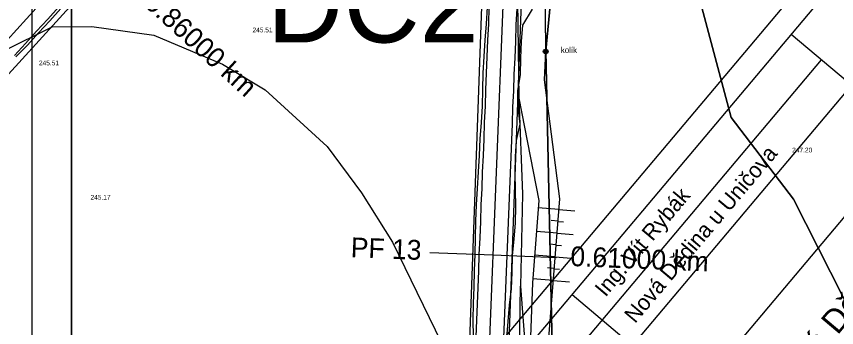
# Model space of a CAD drawing. Extents: x -555887 to -552101, y -1100251 to -1096546.
# Drawn here: x -554315.6 to -554212, y -1097004.2 to -1096964.9 of the extents above; entities that cross this region are included whole.
import ezdxf

# ---------------------------------------------------------------- set-up
doc = ezdxf.new("R2010")
doc.units = 0
for name, color, linetype in [('PARCELY_cesty', 7, 'Continuous'), ('PARCELY_VHO', 7, 'Continuous'), ('POLYGONY_POPIS_CESTY', 7, 'Continuous'), ('POLYGONY_SITUACE_PF', 7, 'Continuous'), ('POLYGONY_SITUACE_PF_POPISY', 7, 'Continuous'), ('POLYGONY_SITUACE_PO', 7, 'Continuous'), ('ram_VC2', 7, 'Continuous'), ('ram_VC6', 7, 'Continuous'), ('vrstevnice', 7, 'Continuous'), ('Výškopis', 7, 'Continuous'), ('ZSST', 7, 'Continuous'), ('zájem', 7, 'Continuous')]:
    doc.layers.add(name, color=color, linetype=linetype)

msp = doc.modelspace()

# ---------------------------------------------------------------- linework, layer by layer
at = {"layer": 'PARCELY_cesty'}
for points in [[(-554879.07, -1097590.15), (-554550.67, -1097229.32), (-554531.76, -1097208.54), (-554275.81, -1096927.3), (-554273.04, -1096923.94), (-554268.63, -1096916.51), (-554265.12, -1096907.97), (-554264.18, -1096901.52)], [(-554235.26, -1097250.21), (-554222.33, -1097095.1), (-554222.18, -1097088.53), (-554223.59, -1097078.8), (-554226.63, -1097069.37), (-554233.34, -1097058.26), (-554245.88, -1097042.06), (-554250.33, -1097033.26), (-554252.75, -1097025.27), (-554253.64, -1097013.94), (-554251.14, -1096944.55), (-554252.47, -1096936.15), (-554254.99, -1096928.04), (-554262.23, -1096914.12), (-554265.12, -1096907.97)], [(-554240.16, -1097243.28), (-554227.33, -1097094.83), (-554227.19, -1097088.83), (-554228.48, -1097079.94), (-554231.21, -1097071.46), (-554237.47, -1097061.09), (-554250.13, -1097044.74), (-554254.99, -1097035.13), (-554257.7, -1097026.2), (-554258.64, -1097014.04), (-554256.15, -1096944.85), (-554257.35, -1096937.29), (-554259.63, -1096929.97), (-554262.61, -1096924.34), (-554273.04, -1096923.94)]]:
    msp.add_lwpolyline(points, dxfattribs=at)
at = {"layer": 'PARCELY_VHO'}
for points in [[(-554130.46, -1097180.06), (-554159.17, -1097101.34), (-554159.64, -1097082.93), (-554163.72, -1097067.19), (-554173.74, -1097050.79), (-554190.63, -1097034.96), (-554197.16, -1097028.05), (-554217.46, -1096987.98), (-554225.33, -1096977.64), (-554234.21, -1096944.26), (-554236.99, -1096909.92), (-554235.22, -1096898.62), (-554228.6, -1096882.13), (-554225.73, -1096869.26), (-554224.9, -1096864.61), (-554220.11, -1096846.63), (-554200.4, -1096831.93), (-554179.17, -1096807.62), (-554142.08, -1096773.53), (-554110.69, -1096747.36), (-554089.18, -1096729.49)], [(-554235.26, -1097250.21), (-554222.33, -1097095.1), (-554222.18, -1097088.53), (-554223.59, -1097078.8), (-554226.63, -1097069.37), (-554233.34, -1097058.26), (-554245.88, -1097042.06), (-554250.33, -1097033.26), (-554252.75, -1097025.27), (-554253.64, -1097013.94), (-554251.14, -1096944.55), (-554252.47, -1096936.15), (-554254.99, -1096928.04), (-554262.23, -1096914.12), (-554265.12, -1096907.97), (-554264.18, -1096901.52), (-554256.59, -1096884.82), (-554225.08, -1096837.14), (-554208.2, -1096823.7)], [(-554200.4, -1096831.93), (-554220.11, -1096846.63), (-554224.9, -1096864.61), (-554233.29, -1096868.06), (-554243.42, -1096872.22), (-554247.48, -1096879.5), (-554255.66, -1096892.57), (-554260.45, -1096913.44), (-554248.68, -1096931.61), (-554247, -1096951.09), (-554248.74, -1096969.23), (-554247.82, -1097012.49), (-554234.69, -1097042.48), (-554228.63, -1097050.04), (-554218.79, -1097074.22), (-554216.52, -1097103.52), (-554219.47, -1097120.44), (-554219.42, -1097159.44)]]:
    msp.add_lwpolyline(points, dxfattribs=at)
at = {"layer": 'POLYGONY_SITUACE_PF'}
for p, q in [((-554263.37, -1096994.69), (-554255.38, -1096995.02)), ((-554255.38, -1096995.02), (-554247.38, -1096995.34))]:
    msp.add_line(p, q, dxfattribs=at)
at = {"layer": 'POLYGONY_SITUACE_PO'}
for p, q in [((-554884.96, -1097592.18), (-554278.08, -1096925.34)), ((-554256.14, -1097013.99), (-554253.57, -1096950.09)), ((-554311.64, -1096965.2), (-554310.24, -1096963.66)), ((-554311.64, -1096965.2), (-554310.24, -1096963.66)), ((-554311.39, -1096965.42), (-554310, -1096963.88)), ((-554256.24, -1096965.79), (-554256.09, -1096963.71)), ((-554255.95, -1096965.8), (-554255.87, -1096963.72)), ((-554255.95, -1096965.8), (-554255.87, -1096963.72)), ((-554252.46, -1096965.94), (-554252.37, -1096963.86)), ((-554252.46, -1096965.94), (-554252.37, -1096963.86)), ((-554251.63, -1096965.98), (-554250.4, -1096963.94)), ((-554313.05, -1096966.74), (-554311.64, -1096965.2)), ((-554313.05, -1096966.74), (-554311.64, -1096965.2)), ((-554312.82, -1096966.94), (-554311.39, -1096965.42)), ((-554256.4, -1096967.87), (-554256.24, -1096965.79)), ((-554256.04, -1096967.88), (-554255.95, -1096965.8)), ((-554256.04, -1096967.88), (-554255.95, -1096965.8)), ((-554252.54, -1096968.03), (-554252.46, -1096965.94)), ((-554252.54, -1096968.03), (-554252.46, -1096965.94)), ((-554251.82, -1096968.05), (-554251.63, -1096965.98)), ((-554314.45, -1096968.28), (-554313.05, -1096966.74)), ((-554314.45, -1096968.28), (-554313.05, -1096966.74)), ((-554314.21, -1096968.5), (-554312.82, -1096966.94)), ((-554256.52, -1096969.95), (-554256.4, -1096967.87)), ((-554256.12, -1096969.97), (-554256.04, -1096967.88)), ((-554256.12, -1096969.97), (-554256.04, -1096967.88)), ((-554252.62, -1096970.11), (-554252.54, -1096968.03)), ((-554252.62, -1096970.11), (-554252.54, -1096968.03)), ((-554251.89, -1096970.14), (-554251.82, -1096968.05)), ((-554315.85, -1096969.82), (-554314.45, -1096968.28)), ((-554315.85, -1096969.82), (-554314.45, -1096968.28)), ((-554315.67, -1096969.98), (-554314.21, -1096968.5)), ((-554256.63, -1096972.03), (-554256.52, -1096969.95)), ((-554256.21, -1096972.05), (-554256.12, -1096969.97)), ((-554256.21, -1096972.05), (-554256.12, -1096969.97)), ((-554252.71, -1096972.19), (-554252.62, -1096970.11)), ((-554252.71, -1096972.19), (-554252.62, -1096970.11)), ((-554251.93, -1096972.22), (-554251.89, -1096970.14)), ((-554256.69, -1096974.11), (-554256.63, -1096972.03)), ((-554256.29, -1096974.13), (-554256.21, -1096972.05)), ((-554256.29, -1096974.13), (-554256.21, -1096972.05)), ((-554252.79, -1096974.27), (-554252.71, -1096972.19)), ((-554252.79, -1096974.27), (-554252.71, -1096972.19)), ((-554252.27, -1096974.29), (-554251.93, -1096972.22)), ((-554256.74, -1096976.2), (-554256.69, -1096974.11)), ((-554256.37, -1096976.21), (-554256.29, -1096974.13)), ((-554256.37, -1096976.21), (-554256.29, -1096974.13)), ((-554252.88, -1096976.35), (-554252.79, -1096974.27)), ((-554252.88, -1096976.35), (-554252.79, -1096974.27)), ((-554252.24, -1096976.38), (-554252.27, -1096974.29)), ((-554256.87, -1096978.28), (-554256.74, -1096976.2)), ((-554256.46, -1096978.29), (-554256.37, -1096976.21)), ((-554256.46, -1096978.29), (-554256.37, -1096976.21)), ((-554252.96, -1096978.43), (-554252.88, -1096976.35)), ((-554252.96, -1096978.43), (-554252.88, -1096976.35)), ((-554251.97, -1096978.47), (-554252.24, -1096976.38)), ((-554257.01, -1096980.36), (-554256.87, -1096978.28)), ((-554256.54, -1096980.37), (-554256.46, -1096978.29)), ((-554256.54, -1096980.37), (-554256.46, -1096978.29)), ((-554253.04, -1096980.51), (-554252.96, -1096978.43)), ((-554253.04, -1096980.51), (-554252.96, -1096978.43)), ((-554252.45, -1096980.54), (-554251.97, -1096978.47)), ((-554257.12, -1096982.44), (-554257.01, -1096980.36)), ((-554256.62, -1096982.46), (-554256.54, -1096980.37)), ((-554256.62, -1096982.46), (-554256.54, -1096980.37)), ((-554253.13, -1096982.6), (-554253.04, -1096980.51)), ((-554253.13, -1096982.6), (-554253.04, -1096980.51)), ((-554252.55, -1096982.62), (-554252.45, -1096980.54)), ((-554257.23, -1096984.52), (-554257.12, -1096982.44)), ((-554256.71, -1096984.54), (-554256.62, -1096982.46)), ((-554256.71, -1096984.54), (-554256.62, -1096982.46)), ((-554253.21, -1096984.68), (-554253.13, -1096982.6)), ((-554253.21, -1096984.68), (-554253.13, -1096982.6)), ((-554252.62, -1096984.7), (-554252.55, -1096982.62)), ((-554257.36, -1096986.6), (-554257.23, -1096984.52)), ((-554256.79, -1096986.62), (-554256.71, -1096984.54)), ((-554256.79, -1096986.62), (-554256.71, -1096984.54)), ((-554253.29, -1096986.76), (-554253.21, -1096984.68)), ((-554253.29, -1096986.76), (-554253.21, -1096984.68)), ((-554252.58, -1096986.79), (-554252.62, -1096984.7)), ((-554257.5, -1096988.68), (-554257.36, -1096986.6)), ((-554256.88, -1096988.7), (-554256.79, -1096986.62)), ((-554256.88, -1096988.7), (-554256.79, -1096986.62)), ((-554253.38, -1096988.84), (-554253.29, -1096986.76)), ((-554253.38, -1096988.84), (-554253.29, -1096986.76)), ((-554252.52, -1096988.88), (-554252.58, -1096986.79)), ((-554257.57, -1096990.76), (-554257.5, -1096988.68)), ((-554256.96, -1096990.78), (-554256.88, -1096988.7)), ((-554256.96, -1096990.78), (-554256.88, -1096988.7)), ((-554253.46, -1096990.92), (-554253.38, -1096988.84)), ((-554253.46, -1096990.92), (-554253.38, -1096988.84)), ((-554252.58, -1096990.96), (-554252.52, -1096988.88)), ((-554257.63, -1096992.84), (-554257.57, -1096990.76)), ((-554257.04, -1096992.86), (-554256.96, -1096990.78)), ((-554257.04, -1096992.86), (-554256.96, -1096990.78)), ((-554253.55, -1096993), (-554253.46, -1096990.92)), ((-554253.55, -1096993), (-554253.46, -1096990.92)), ((-554252.75, -1096993.04), (-554252.58, -1096990.96)), ((-554257.67, -1096994.92), (-554257.63, -1096992.84)), ((-554257.13, -1096994.95), (-554257.04, -1096992.86)), ((-554257.13, -1096994.95), (-554257.04, -1096992.86)), ((-554253.63, -1096995.09), (-554253.55, -1096993)), ((-554253.63, -1096995.09), (-554253.55, -1096993)), ((-554252.93, -1096995.11), (-554252.75, -1096993.04)), ((-554257.72, -1096997.01), (-554257.67, -1096994.92)), ((-554257.21, -1096997.03), (-554257.13, -1096994.95)), ((-554257.21, -1096997.03), (-554257.13, -1096994.95)), ((-554253.71, -1096997.17), (-554253.63, -1096995.09)), ((-554253.71, -1096997.17), (-554253.63, -1096995.09)), ((-554252.98, -1096997.2), (-554252.93, -1096995.11)), ((-554257.78, -1096999.09), (-554257.72, -1096997.01)), ((-554257.29, -1096999.11), (-554257.21, -1096997.03)), ((-554257.29, -1096999.11), (-554257.21, -1096997.03)), ((-554253.8, -1096999.25), (-554253.71, -1096997.17)), ((-554253.8, -1096999.25), (-554253.71, -1096997.17)), ((-554253.08, -1096999.28), (-554252.98, -1096997.2)), ((-554257.85, -1097001.17), (-554257.78, -1096999.09)), ((-554257.38, -1097001.19), (-554257.29, -1096999.11)), ((-554257.38, -1097001.19), (-554257.29, -1096999.11)), ((-554253.88, -1097001.33), (-554253.8, -1096999.25)), ((-554253.88, -1097001.33), (-554253.8, -1096999.25)), ((-554253.31, -1097001.35), (-554253.08, -1096999.28)), ((-554257.89, -1097003.26), (-554257.85, -1097001.17)), ((-554257.46, -1097003.27), (-554257.38, -1097001.19)), ((-554257.46, -1097003.27), (-554257.38, -1097001.19)), ((-554253.96, -1097003.41), (-554253.88, -1097001.33)), ((-554253.96, -1097003.41), (-554253.88, -1097001.33)), ((-554253.49, -1097003.43), (-554253.31, -1097001.35)), ((-554257.85, -1097005.34), (-554257.89, -1097003.26)), ((-554257.55, -1097005.35), (-554257.46, -1097003.27)), ((-554257.55, -1097005.35), (-554257.46, -1097003.27)), ((-554254.05, -1097005.49), (-554253.96, -1097003.41)), ((-554254.05, -1097005.49), (-554253.96, -1097003.41)), ((-554253.64, -1097005.51), (-554253.49, -1097003.43))]:
    msp.add_line(p, q, dxfattribs=at)
at = {"layer": 'ram_VC2'}
for p, q in [((-554279.7, -1097071.82), (-554163.8, -1096934.09)), ((-554217.74, -1096967.12), (-554171.83, -1097005.76)), ((-554291.17, -1097062.16), (-554213.91, -1096970.34)), ((-554287.35, -1097065.38), (-554210.09, -1096973.56)), ((-554245.42, -1097000.02), (-554237.77, -1097006.46))]:
    msp.add_line(p, q, dxfattribs=at)
for points in [[(-554299.23, -1097059.3), (-554179.47, -1096916.99), (-554128.97, -1096959.48), (-554248.73, -1097101.8)], [(-554295, -1097058.94), (-554179.11, -1096921.22), (-554133.2, -1096959.85), (-554249.09, -1097097.57)]]:
    msp.add_lwpolyline(points, close=True, dxfattribs=at)
at = {"layer": 'ram_VC6'}
for points in [[(-553956.64, -1096765.72), (-554313.64, -1096765.72), (-554313.64, -1097395.72), (-553956.64, -1097395.72)], [(-553961.64, -1096770.72), (-554308.64, -1096770.72), (-554308.64, -1097390.72), (-553961.64, -1097390.72)]]:
    msp.add_lwpolyline(points, close=True, dxfattribs=at)
for points in [[(-553956.64, -1096765.72), (-554313.64, -1096765.72), (-554313.64, -1097395.72), (-553956.64, -1097395.72), (-553956.64, -1096765.72)], [(-553956.64, -1096765.72), (-554313.64, -1096765.72), (-554313.64, -1097395.72), (-553956.64, -1097395.72), (-553956.64, -1096765.72)], [(-553961.64, -1097390.72), (-554308.64, -1097390.72), (-554308.64, -1096770.72), (-553961.64, -1096770.72), (-553961.64, -1097390.72)], [(-553961.64, -1097185.72), (-553961.64, -1097390.72), (-554308.64, -1097390.72), (-554308.64, -1096770.72), (-553961.64, -1096770.72), (-553961.64, -1096975.72), (-553961.64, -1097185.72)]]:
    msp.add_lwpolyline(points, dxfattribs=at)
at = {"layer": 'vrstevnice'}
msp.add_lwpolyline([(-554317.19, -1096969.22), (-554311.07, -1096966.19), (-554306.06, -1096966.14), (-554298.26, -1096967.23), (-554289.58, -1096970.91), (-554284.16, -1096974.15), (-554276.35, -1096981.3), (-554272.02, -1096987.15), (-554268.11, -1096993.42), (-554255.75, -1097018.76)], dxfattribs=at)
at = {"layer": 'ZSST'}
for p, q in [((-554247.08, -1096989.26), (-554249.7, -1096989.05)), ((-554247.08, -1096989.28), (-554245.05, -1096989.44)), ((-554247.19, -1096990.75), (-554248.07, -1096990.68)), ((-554247.2, -1096990.78), (-554246.52, -1096990.83)), ((-554247.31, -1096992.25), (-554249.93, -1096992.04)), ((-554247.32, -1096992.27), (-554245.28, -1096992.44)), ((-554247.43, -1096993.74), (-554248.3, -1096993.67)), ((-554247.43, -1096993.77), (-554246.76, -1096993.82)), ((-554247.55, -1096995.24), (-554250.15, -1096995.03)), ((-554247.55, -1096995.26), (-554245.52, -1096995.43)), ((-554247.67, -1096996.73), (-554248.53, -1096996.66)), ((-554247.67, -1096996.76), (-554246.99, -1096996.81)), ((-554247.79, -1096998.23), (-554250.38, -1096998.02)), ((-554247.79, -1096998.26), (-554245.76, -1096998.42))]:
    msp.add_line(p, q, dxfattribs=at)
for points in [[(-554248.75, -1096969.32), (-554248.83, -1096959.93), (-554247.06, -1096950.99), (-554246.71, -1096943.72), (-554248.72, -1096931.57), (-554260.49, -1096913.37), (-554262.48, -1096905.88), (-554262.15, -1096901.68), (-554255.84, -1096892.45), (-554252.43, -1096885.13), (-554239.88, -1096862.77), (-554230.92, -1096848.31), (-554223.97, -1096838.55), (-554218.79, -1096832.76), (-554212.02, -1096827.16), (-554202.06, -1096819.83), (-554190.67, -1096813.97), (-554190.64, -1096810.55)], [(-554252.3, -1096962.91), (-554252.15, -1096975.19), (-554251.67, -1096987.35), (-554251.95, -1096998.96), (-554250.9, -1097012.23), (-554249.88, -1097021.55), (-554248.64, -1097027.57), (-554246.07, -1097036.01), (-554240.86, -1097045.62), (-554233.57, -1097053.76), (-554226.53, -1097064.63), (-554223.28, -1097073.72), (-554220.82, -1097084.32), (-554219.54, -1097095.27), (-554223.32, -1097113.64)], [(-554218.54, -1097175.67), (-554218.88, -1097171.11), (-554218.23, -1097160.44), (-554219.16, -1097151.75), (-554218.79, -1097120.84), (-554218.38, -1097111.65), (-554216.83, -1097104.6), (-554216.54, -1097100.8), (-554217.26, -1097093.11), (-554218.21, -1097084.79), (-554219.72, -1097074.34), (-554228.66, -1097049.95), (-554233.75, -1097046.05), (-554234.74, -1097042.43), (-554239.98, -1097031.94), (-554247.7, -1097012.53), (-554248.49, -1097007.1), (-554246.97, -1096987.92), (-554248.9, -1096972.89), (-554248.75, -1096969.32)], [(-554252.15, -1096975.19), (-554249.63, -1096988.14), (-554250.42, -1096998.55), (-554250.9, -1097012.23)], [(-554223.32, -1097113.64), (-554221.4, -1097095.79), (-554222, -1097084.45), (-554224.47, -1097074.24), (-554228.76, -1097064.88), (-554234.93, -1097055.2), (-554242.22, -1097045.94), (-554248.05, -1097037.26), (-554252.18, -1097022.38), (-554252.13, -1097012.54), (-554251.95, -1096998.96)]]:
    msp.add_lwpolyline(points, dxfattribs=at)
for radius in [0.3, 0.15]:
    msp.add_circle((-554248.75, -1096969.32), radius, dxfattribs=at)
at = {"layer": 'zájem'}
for points in [[(-554197.16, -1097028.05), (-554217.46, -1096987.98), (-554225.33, -1096977.64), (-554234.21, -1096944.26), (-554236.99, -1096909.92), (-554235.22, -1096898.62), (-554228.6, -1096882.13), (-554225.73, -1096869.26), (-554224.9, -1096864.61), (-554233.29, -1096868.06), (-554243.42, -1096872.22), (-554247.48, -1096879.5), (-554255.66, -1096892.57), (-554260.45, -1096913.44), (-554248.68, -1096931.61), (-554247, -1096951.09), (-554248.74, -1096969.23), (-554247.82, -1097012.49)], [(-554247.82, -1097012.49), (-554248.74, -1096969.23), (-554247, -1096951.09), (-554248.68, -1096931.61), (-554260.45, -1096913.44), (-554255.66, -1096892.57), (-554247.48, -1096879.5), (-554243.42, -1096872.22), (-554233.29, -1096868.06), (-554224.9, -1096864.61), (-554225.73, -1096869.26), (-554228.6, -1096882.13), (-554235.22, -1096898.62), (-554236.99, -1096909.92), (-554234.21, -1096944.26), (-554225.33, -1096977.64), (-554217.46, -1096987.98), (-554197.16, -1097028.05)]]:
    msp.add_lwpolyline(points, dxfattribs=at)

# ---------------------------------------------------------------- texts
at = {"layer": 'POLYGONY_POPIS_CESTY'}
msp.add_text('DC2', height=10, rotation=360, dxfattribs=at).set_placement((-554283.97, -1096968.16))
at = {"layer": 'POLYGONY_SITUACE_PF_POPISY'}
for s, rotation, p in [('0.86000 km', 317.6947, (-554299.57, -1096963.45)), ('PF 13', 357.6967, (-554273.4, -1096995.29)), ('0.61000 km', 357.6967, (-554245.67, -1096996.41))]:
    msp.add_text(s, height=2.5, rotation=rotation, dxfattribs=at).set_placement(p)
at = {"layer": 'ram_VC2'}
for s, height, p in [('Komplexní pozemkové úpravy v  k.ú. Nová Dědina u Uničova', 3, (-554261.57, -1097064.25)), ('Nová Dědina u Uničova', 2, (-554237.46, -1097003.76)), ('Ing. Vít Rybák', 2, (-554241.19, -1097000.43))]:
    msp.add_text(s, height=height, rotation=49.9197, dxfattribs=at).set_placement(p)
at = {"layer": 'Výškopis'}
for s, p in [('245.51', (-554285.78, -1096966.88)), ('245.51', (-554312.75, -1096971.05)), ('247.20', (-554217.62, -1096982.06)), ('245.17', (-554306.24, -1096988.03))]:
    msp.add_text(s, height=0.6, dxfattribs=at).set_placement(p)
at = {"layer": 'ZSST'}
msp.add_text('kolík', height=0.75, dxfattribs=at).set_placement((-554246.84, -1096969.5))

doc.saveas('drawing.dxf')
